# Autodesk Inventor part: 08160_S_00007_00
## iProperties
Created: 2010-06
Part Number: 08160_S_00007_00
Document SubType Name: Blech
Designer: Administrator
Density: 1 g/cm^3
Flat Pattern Width: 2.5 cm
Flat Pattern Length: 46.772 cm
Flat Pattern Area: 116.93 cm^2
Sheet Metal Rule: Standard
Author: Administrator
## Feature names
1. Sweeping1
2. Sweeping2
